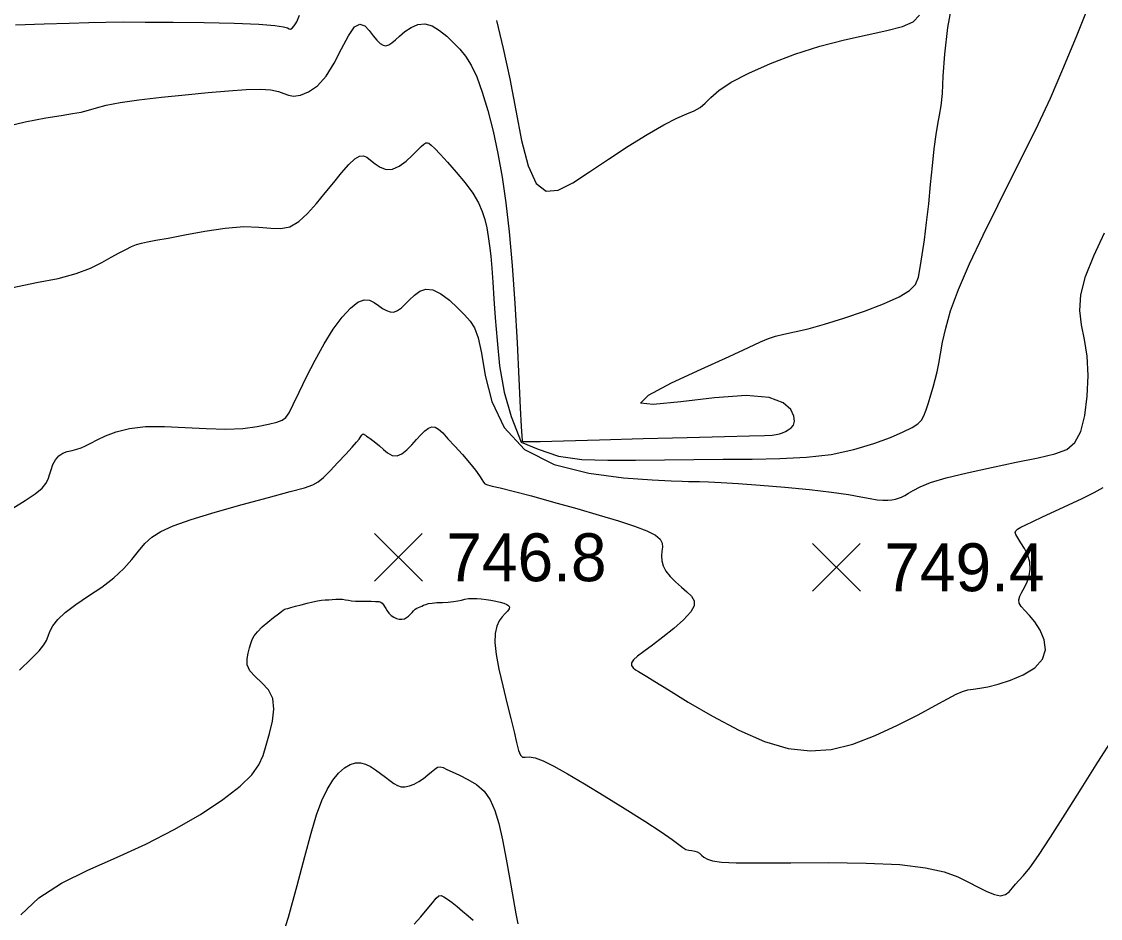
# Model space of a CAD drawing. Extents: x 2566142 to 2571431, y 418755 to 421584.
# Drawn here: x 2567172.5 to 2567510.6, y 420429 to 420710 of the extents above; entities that cross this region are included whole.
import ezdxf

# ---------------------------------------------------------------- set-up
doc = ezdxf.new("R2010")
doc.units = 0
for name, color, linetype in [('Contour_ADS_Major', 7, 'Continuous'), ('Contour_ADS_Minor', 7, 'Continuous'), ('Contour_ADS_Spot_Elevation', 7, 'Continuous')]:
    doc.layers.add(name, color=color, linetype=linetype)

# ---------------------------------------------------------------- blocks, each defined once
blk = doc.blocks.new('S750')
at = {"layer": 'Contour_ADS_Spot_Elevation'}
for p, q in [((-0.5, 0.498), (0.5, -0.498)), ((-0.498, -0.5), (0.498, 0.5))]:
    blk.add_line(p, q, dxfattribs=at)

msp = doc.modelspace()

# ---------------------------------------------------------------- linework, layer by layer
at = {"layer": 'Contour_ADS_Major'}
for points in [[(2567288.05, 420618.97), (2567289.21, 420618.95), (2567290.36, 420619.41), (2567291.53, 420620.26), (2567292.77, 420621.43), (2567294.12, 420622.79), (2567295.61, 420624.23), (2567297.28, 420625.45), (2567299.2, 420626.13), (2567301.42, 420625.94), (2567303.93, 420624.68), (2567306.57, 420622.66), (2567309.11, 420620.31), (2567311.33, 420618.06), (2567313.07, 420616.14), (2567314.43, 420614), (2567315.55, 420610.9), (2567316.59, 420606.07), (2567317.81, 420599.12), (2567319.91, 420590.95), (2567323.74, 420582.79), (2567330.09, 420575.9), (2567339.38, 420571.21), (2567350.31, 420568.44), (2567361.14, 420567.04), (2567370.15, 420566.42), (2567376.09, 420566.1), (2567379.51, 420565.94), (2567381.46, 420565.88), (2567382.95, 420565.86), (2567384.9, 420565.83), (2567387.72, 420565.74), (2567391.68, 420565.55), (2567397.06, 420565.22), (2567403.95, 420564.71), (2567411.69, 420564.07), (2567419.42, 420563.34), (2567426.27, 420562.56), (2567431.59, 420561.8), (2567435.52, 420561.11), (2567438.42, 420560.54), (2567440.62, 420560.14), (2567442.43, 420559.97), (2567443.94, 420559.98), (2567445.22, 420560.12), (2567446.32, 420560.35), (2567447.3, 420560.63), (2567448.25, 420560.99), (2567449.26, 420561.48), (2567450.42, 420562.17), (2567451.89, 420563.08), (2567454.05, 420564.2), (2567457.34, 420565.52), (2567462.19, 420567.01), (2567468.81, 420568.63), (2567476.47, 420570.29), (2567484.21, 420571.88), (2567491.06, 420573.28), (2567496.29, 420574.5), (2567500.01, 420575.94), (2567502.59, 420578.12), (2567504.38, 420581.56), (2567505.67, 420586.57), (2567506.46, 420592.64), (2567506.74, 420599.06), (2567506.44, 420605.12), (2567505.61, 420610.31), (2567504.67, 420614.93), (2567504.1, 420619.45), (2567504.39, 420624.38), (2567505.92, 420630.1), (2567508.51, 420636.59), (2567511.88, 420643.75)], [(2567169.79, 420557.49), (2567173.66, 420559.86), (2567176.82, 420561.99), (2567178.93, 420563.74), (2567180.16, 420565.21), (2567180.84, 420566.57), (2567181.28, 420567.99), (2567181.76, 420569.56), (2567182.36, 420571.19), (2567183.15, 420572.69), (2567184.16, 420573.92), (2567185.42, 420574.74), (2567186.86, 420575.25), (2567188.36, 420575.61), (2567189.82, 420575.95), (2567191.18, 420576.41), (2567192.58, 420577.03), (2567194.21, 420577.84), (2567196.24, 420578.88), (2567198.87, 420580.13), (2567202.19, 420581.4), (2567206.32, 420582.46), (2567211.36, 420583.09), (2567217.32, 420583.14), (2567223.82, 420582.82), (2567230.38, 420582.42), (2567236.54, 420582.24), (2567241.89, 420582.48), (2567246.34, 420583.06), (2567249.87, 420583.79), (2567252.47, 420584.5), (2567254.19, 420585.11), (2567255.36, 420585.94), (2567256.38, 420587.41), (2567257.66, 420589.95), (2567259.51, 420593.81), (2567261.85, 420598.63), (2567264.52, 420603.87), (2567267.35, 420609), (2567270.21, 420613.56), (2567272.97, 420617.35), (2567275.56, 420620.22), (2567277.87, 420622.05), (2567279.85, 420622.77), (2567281.55, 420622.63), (2567283.03, 420621.93), (2567284.37, 420620.99), (2567285.64, 420620.1), (2567286.86, 420619.39), (2567288.05, 420618.97)]]:
    msp.add_lwpolyline(points, dxfattribs=at)
at = {"layer": 'Contour_ADS_Minor'}
for points in [[(2567283.85, 420704.13), (2567284.87, 420703.14), (2567285.81, 420702.56), (2567286.71, 420702.4), (2567287.59, 420702.64), (2567288.54, 420703.26), (2567289.65, 420704.2), (2567290.99, 420705.41), (2567292.65, 420706.8), (2567294.57, 420708.11), (2567296.68, 420709.03), (2567298.92, 420709.26), (2567301.22, 420708.59), (2567303.52, 420707.2), (2567305.76, 420705.36), (2567307.87, 420703.34), (2567309.82, 420701.32), (2567311.64, 420699.08), (2567313.39, 420696.28), (2567315.13, 420692.62), (2567316.88, 420687.86), (2567318.62, 420682.13), (2567320.27, 420675.65), (2567321.8, 420668.64), (2567323.14, 420661.22), (2567324.31, 420653.14), (2567325.35, 420644.04), (2567326.26, 420633.57), (2567327.07, 420621.66), (2567327.78, 420609.35), (2567328.36, 420598), (2567328.79, 420588.93), (2567329.07, 420583.11), (2567329.23, 420580.02), (2567329.34, 420578.77), (2567329.43, 420578.47), (2567329.74, 420578.38), (2567331.23, 420578.36), (2567335.04, 420578.44), (2567342.3, 420578.63), (2567353.59, 420578.94), (2567367.25, 420579.32), (2567381.03, 420579.7), (2567392.73, 420580.01), (2567400.64, 420580.21), (2567405.28, 420580.32), (2567407.71, 420580.41), (2567408.99, 420580.55), (2567410, 420580.77), (2567410.95, 420581.08), (2567411.86, 420581.5), (2567412.76, 420582.02), (2567413.64, 420582.66), (2567414.36, 420583.52), (2567414.72, 420584.72), (2567414.54, 420586.35), (2567413.54, 420588.44), (2567411.16, 420590.56), (2567406.73, 420592.18), (2567399.6, 420592.79), (2567389.67, 420592.11), (2567379.06, 420590.84), (2567370.45, 420589.96), (2567366.5, 420590.43), (2567369.01, 420592.89), (2567376.22, 420596.75), (2567385.5, 420601.1), (2567394.2, 420605.02), (2567400.28, 420607.8), (2567404.09, 420609.58), (2567406.61, 420610.65), (2567408.77, 420611.36), (2567411.4, 420612), (2567414.75, 420612.73), (2567418.95, 420613.72), (2567424.1, 420615.12), (2567430.18, 420617), (2567436.59, 420619.22), (2567442.61, 420621.53), (2567447.5, 420623.73), (2567450.72, 420625.68), (2567452.57, 420627.62), (2567453.53, 420629.91), (2567454.12, 420632.89), (2567454.72, 420636.83), (2567455.39, 420641.59), (2567456.09, 420647), (2567456.76, 420652.84), (2567457.37, 420658.88), (2567457.94, 420664.77), (2567458.49, 420670.12), (2567459.05, 420674.54), (2567459.61, 420677.85), (2567460.16, 420680.6), (2567460.65, 420683.53), (2567461.04, 420687.41), (2567461.34, 420692.81), (2567461.82, 420699.77), (2567462.78, 420708.15), (2567464.56, 420717.81)], [(2567453.35, 420583.95), (2567454.45, 420585.08), (2567455.24, 420586.49), (2567455.99, 420588.34), (2567456.74, 420590.56), (2567457.47, 420592.98), (2567458.15, 420595.43), (2567458.78, 420597.8), (2567459.37, 420600.22), (2567459.93, 420602.86), (2567460.49, 420605.88), (2567461.13, 420609.49), (2567462.08, 420613.89), (2567463.62, 420619.32), (2567466.05, 420626.03), (2567469.55, 420634.1), (2567473.8, 420643.07), (2567478.41, 420652.37), (2567482.95, 420661.38), (2567487.13, 420669.71), (2567491.04, 420677.73), (2567494.87, 420686), (2567498.83, 420695.08), (2567503.05, 420705.32), (2567507.46, 420716.2)], [(2567187.41, 420709.51), (2567193.57, 420709.68), (2567198.88, 420709.78), (2567204.42, 420709.83), (2567211.23, 420709.82), (2567219.99, 420709.76), (2567229.74, 420709.63), (2567239.15, 420709.43), (2567246.85, 420709.14), (2567251.86, 420708.75), (2567254.59, 420708.34), (2567255.84, 420707.96), (2567256.36, 420707.7), (2567256.82, 420707.63), (2567257.35, 420707.88), (2567257.99, 420708.6), (2567258.75, 420709.9), (2567259.65, 420711.92)], [(2567321.35, 420710.25), (2567323.45, 420701.54), (2567325.5, 420692), (2567327.36, 420682.09), (2567329.21, 420672.67), (2567331.26, 420664.72), (2567333.75, 420659.22), (2567336.89, 420656.86), (2567340.71, 420657.17), (2567345.24, 420659.43), (2567350.5, 420662.88), (2567356.43, 420666.86), (2567362.61, 420670.9), (2567368.55, 420674.63), (2567373.76, 420677.65), (2567377.86, 420679.7), (2567380.98, 420681.03), (2567383.32, 420682.02), (2567385.14, 420683.05), (2567386.7, 420684.43), (2567388.48, 420686.21), (2567391.03, 420688.39), (2567394.87, 420690.95), (2567400.36, 420693.84), (2567407.16, 420696.85), (2567414.77, 420699.74), (2567422.66, 420702.28), (2567430.36, 420704.27), (2567437.48, 420705.85), (2567443.66, 420707.18), (2567448.53, 420708.46), (2567451.87, 420709.91), (2567453.92, 420711.92)], [(2567165.3, 420676.58), (2567173.62, 420678.5), (2567180.11, 420679.77), (2567184.93, 420680.58), (2567188.5, 420681.12), (2567191.22, 420681.61), (2567193.54, 420682.22), (2567195.97, 420682.94), (2567199.08, 420683.74), (2567203.41, 420684.59), (2567209.32, 420685.44), (2567216.34, 420686.27), (2567223.79, 420687.04), (2567231, 420687.73), (2567237.41, 420688.29), (2567242.85, 420688.66), (2567247.29, 420688.79), (2567250.66, 420688.6), (2567253.01, 420688.09), (2567254.68, 420687.44), (2567256.12, 420686.87), (2567257.74, 420686.63), (2567259.89, 420686.92), (2567262.45, 420687.94), (2567265.21, 420689.86), (2567267.94, 420692.85), (2567270.49, 420696.93), (2567272.81, 420701.43), (2567274.92, 420705.49), (2567276.83, 420708.28), (2567278.55, 420709.2), (2567280.1, 420708.62), (2567281.49, 420707.19), (2567282.73, 420705.52), (2567283.85, 420704.13)], [(2567170.65, 420708.95), (2567179.64, 420709.27), (2567187.41, 420709.51)], [(2567169.81, 420626.6), (2567177.23, 420628.2), (2567184.02, 420629.48), (2567189.62, 420630.99), (2567194.11, 420632.71), (2567197.71, 420634.47), (2567200.64, 420636.11), (2567203.08, 420637.49), (2567205.16, 420638.6), (2567206.95, 420639.46), (2567208.55, 420640.1), (2567210.08, 420640.56), (2567211.94, 420640.96), (2567214.57, 420641.44), (2567218.41, 420642.15), (2567223.7, 420643.17), (2567229.9, 420644.28), (2567236.29, 420645.22), (2567242.13, 420645.71), (2567246.85, 420645.59), (2567250.63, 420645.23), (2567253.76, 420645.1), (2567256.59, 420645.68), (2567259.38, 420647.32), (2567262.16, 420649.84), (2567264.93, 420652.93), (2567267.66, 420656.28), (2567270.32, 420659.59), (2567272.82, 420662.62), (2567275.07, 420665.15), (2567276.96, 420666.94), (2567278.43, 420667.83), (2567279.63, 420667.94), (2567280.72, 420667.44), (2567281.89, 420666.53), (2567283.28, 420665.39), (2567284.91, 420664.32), (2567286.74, 420663.64), (2567288.74, 420663.68), (2567290.88, 420664.61), (2567293, 420666.18), (2567294.96, 420667.99), (2567296.59, 420669.64), (2567297.78, 420670.83), (2567298.61, 420671.56), (2567299.2, 420671.92), (2567299.68, 420671.99), (2567300.18, 420671.82), (2567300.88, 420671.28), (2567301.97, 420670.21), (2567303.64, 420668.44), (2567305.98, 420665.89), (2567308.72, 420662.79), (2567311.48, 420659.44), (2567313.89, 420656.17), (2567315.66, 420653.2), (2567316.87, 420650.49), (2567317.68, 420647.91), (2567318.27, 420645.35), (2567318.75, 420642.67), (2567319.17, 420639.75), (2567319.55, 420636.47), (2567319.88, 420632.69), (2567320.18, 420628.29), (2567320.51, 420623.13), (2567320.93, 420617.11), (2567321.5, 420610.08), (2567322.32, 420602.09), (2567323.69, 420593.84), (2567325.95, 420586.2), (2567329.09, 420578.14), (2567334.43, 420576), (2567340.73, 420573.76), (2567348.08, 420572.78), (2567356.22, 420572.53), (2567364.91, 420572.52), (2567373.94, 420572.62), (2567383.15, 420572.76), (2567392.36, 420572.86), (2567401.4, 420572.9), (2567410.14, 420573.03), (2567418.45, 420573.45), (2567426.22, 420574.35), (2567433.29, 420575.85), (2567439.53, 420577.73), (2567444.75, 420579.7), (2567448.8, 420581.47), (2567451.57, 420582.83), (2567453.35, 420583.95)], [(2567261.17, 420563.89), (2567263.82, 420564.77), (2567265.51, 420565.73), (2567267.08, 420567.13), (2567269.18, 420569.25), (2567271.64, 420571.81), (2567274.08, 420574.4), (2567276.12, 420576.61), (2567277.48, 420578.16), (2567278.26, 420579.11), (2567278.65, 420579.65), (2567278.84, 420579.98), (2567279, 420580.24), (2567279.16, 420580.45), (2567279.31, 420580.62), (2567279.44, 420580.72), (2567279.55, 420580.76), (2567279.66, 420580.74), (2567279.77, 420580.69), (2567279.89, 420580.6), (2567280.05, 420580.49), (2567280.28, 420580.33), (2567280.61, 420580.1), (2567281.09, 420579.78), (2567281.73, 420579.33), (2567282.55, 420578.73), (2567283.52, 420577.97), (2567284.63, 420577.01), (2567285.88, 420575.87), (2567287.23, 420574.8), (2567288.67, 420574.05), (2567290.18, 420573.91), (2567291.72, 420574.55), (2567293.27, 420575.8), (2567294.79, 420577.39), (2567296.24, 420579.04), (2567297.6, 420580.52), (2567298.87, 420581.72), (2567300.03, 420582.56), (2567301.1, 420582.96), (2567302.1, 420582.87), (2567303.17, 420582.25), (2567304.47, 420581.06), (2567306.14, 420579.28), (2567308.28, 420576.95), (2567310.64, 420574.32), (2567312.91, 420571.7), (2567314.77, 420569.41), (2567315.99, 420567.68), (2567316.72, 420566.47), (2567317.22, 420565.66), (2567317.72, 420565.14), (2567318.51, 420564.79), (2567319.96, 420564.41), (2567322.49, 420563.83), (2567326.52, 420562.85), (2567332.26, 420561.33), (2567339.17, 420559.44), (2567346.5, 420557.37), (2567353.52, 420555.33), (2567359.6, 420553.5), (2567364.58, 420551.87), (2567368.43, 420550.41), (2567371.11, 420549.06), (2567372.64, 420547.8), (2567373.29, 420546.57), (2567373.36, 420545.33), (2567373.19, 420544.01), (2567373.06, 420542.59), (2567373.13, 420541.06), (2567373.52, 420539.45), (2567374.37, 420537.79), (2567375.72, 420536.08), (2567377.43, 420534.39), (2567379.27, 420532.76), (2567381, 420531.26), (2567382.41, 420529.89), (2567383.25, 420528.52), (2567383.26, 420526.95), (2567382.2, 420525), (2567379.94, 420522.55), (2567376.85, 420519.81), (2567373.44, 420517.08), (2567370.19, 420514.62), (2567367.53, 420512.65), (2567365.54, 420511.14), (2567364.22, 420509.97), (2567363.59, 420509.03), (2567363.6, 420508.23), (2567364.11, 420507.52), (2567364.93, 420506.89), (2567365.88, 420506.31), (2567366.89, 420505.7), (2567368.4, 420504.77), (2567370.98, 420503.18), (2567375.19, 420500.57), (2567381.38, 420496.77), (2567388.98, 420492.32), (2567397.23, 420487.96), (2567405.35, 420484.39), (2567412.76, 420482.21)], [(2567171.83, 420506.75), (2567175.57, 420510.28), (2567178.06, 420512.85), (2567179.51, 420514.66), (2567180.31, 420516.06), (2567180.82, 420517.37), (2567181.41, 420518.88), (2567182.33, 420520.63), (2567183.86, 420522.62), (2567186.23, 420524.87), (2567189.58, 420527.34), (2567193.55, 420530.01), (2567197.66, 420532.81), (2567201.44, 420535.69), (2567204.53, 420538.59), (2567207.03, 420541.41), (2567209.17, 420544.05), (2567211.19, 420546.39), (2567213.35, 420548.39), (2567216.14, 420550.19), (2567220.07, 420551.99), (2567225.67, 420553.97), (2567233.18, 420556.26), (2567241.66, 420558.65), (2567249.91, 420560.88), (2567256.71, 420562.68), (2567261.17, 420563.89)], [(2567412.76, 420482.21), (2567419.6, 420481.43), (2567426.23, 420481.94), (2567432.97, 420483.61), (2567440.03, 420486.26), (2567447.03, 420489.48), (2567453.45, 420492.77), (2567458.78, 420495.67), (2567462.65, 420497.79), (2567465.35, 420499.19), (2567467.31, 420500.05), (2567468.97, 420500.55), (2567470.71, 420500.84), (2567472.76, 420501.11), (2567475.29, 420501.55), (2567478.47, 420502.32), (2567482.34, 420503.57), (2567486.39, 420505.31), (2567489.97, 420507.52), (2567492.44, 420510.15), (2567493.33, 420513.15), (2567492.92, 420516.29), (2567491.65, 420519.29), (2567489.99, 420521.91), (2567488.33, 420523.93), (2567486.87, 420525.46), (2567485.73, 420526.67), (2567485.06, 420527.73), (2567484.95, 420528.78), (2567485.29, 420529.92), (2567485.93, 420531.2), (2567486.74, 420532.68), (2567487.56, 420534.4), (2567488.23, 420536.34), (2567488.59, 420538.41), (2567488.49, 420540.58), (2567487.83, 420542.77), (2567486.8, 420544.85), (2567485.67, 420546.7), (2567484.68, 420548.19), (2567484.07, 420549.23), (2567483.85, 420549.92), (2567484.04, 420550.43), (2567484.63, 420550.92), (2567485.64, 420551.51), (2567487.18, 420552.31), (2567489.39, 420553.38), (2567492.4, 420554.78), (2567496.25, 420556.56), (2567500.55, 420558.54), (2567504.82, 420560.56), (2567508.56, 420562.4), (2567511.44, 420563.94)], [(2567172.31, 420430.15), (2567177.89, 420435.45), (2567185.02, 420440.04), (2567193.32, 420444.14), (2567202.3, 420448.1), (2567211.48, 420452.24), (2567220.37, 420456.79), (2567228.54, 420461.55), (2567235.57, 420466.19), (2567241.02, 420470.39), (2567244.66, 420473.94), (2567246.86, 420477.05), (2567248.18, 420480.05), (2567249.16, 420483.26), (2567250.23, 420486.9), (2567251.16, 420490.76), (2567251.62, 420494.52), (2567251.25, 420497.88), (2567249.85, 420500.6), (2567247.82, 420502.81), (2567245.7, 420504.72), (2567244.04, 420506.53), (2567243.25, 420508.42), (2567243.17, 420510.31), (2567243.52, 420512.13), (2567243.99, 420513.75), (2567244.39, 420515.12), (2567244.8, 420516.33), (2567245.42, 420517.51), (2567246.43, 420518.8), (2567247.93, 420520.28), (2567249.71, 420521.83), (2567251.49, 420523.26), (2567252.98, 420524.41), (2567253.96, 420525.15), (2567254.5, 420525.55), (2567254.77, 420525.72), (2567254.91, 420525.77), (2567255.06, 420525.83), (2567255.37, 420525.92), (2567255.94, 420526.09), (2567256.92, 420526.37), (2567258.36, 420526.77), (2567260.12, 420527.26), (2567261.98, 420527.74), (2567263.74, 420528.16), (2567265.24, 420528.45)], [(2567265.24, 420528.45), (2567266.51, 420528.64), (2567267.65, 420528.76), (2567268.75, 420528.84), (2567269.88, 420528.92), (2567271.02, 420528.98), (2567272.11, 420528.99), (2567273.12, 420528.95), (2567274.03, 420528.82), (2567274.93, 420528.66), (2567275.93, 420528.49), (2567277.17, 420528.37), (2567278.7, 420528.33), (2567280.38, 420528.34), (2567282.02, 420528.35), (2567283.42, 420528.32), (2567284.43, 420528.22), (2567285.11, 420528.02), (2567285.56, 420527.71), (2567285.91, 420527.27), (2567286.24, 420526.7), (2567286.62, 420526.03), (2567287.07, 420525.31), (2567287.64, 420524.59), (2567288.35, 420523.92), (2567289.16, 420523.35), (2567290.02, 420522.92), (2567290.89, 420522.69), (2567291.71, 420522.69), (2567292.47, 420522.88), (2567293.16, 420523.24), (2567293.8, 420523.71), (2567294.36, 420524.26), (2567294.88, 420524.84), (2567295.37, 420525.38), (2567295.87, 420525.84), (2567296.38, 420526.17), (2567296.9, 420526.42), (2567297.44, 420526.63), (2567297.97, 420526.84), (2567298.51, 420527.08), (2567299.15, 420527.35), (2567299.99, 420527.6), (2567301.14, 420527.79), (2567302.66, 420527.91), (2567304.4, 420527.99), (2567306.19, 420528.08), (2567307.84, 420528.22), (2567309.21, 420528.45), (2567310.37, 420528.72), (2567311.44, 420528.98), (2567312.55, 420529.18), (2567313.78, 420529.26), (2567315.14, 420529.23), (2567316.58, 420529.11), (2567318.09, 420528.92), (2567319.61, 420528.68), (2567321.09, 420528.39), (2567322.46, 420528.07), (2567323.64, 420527.72), (2567324.57, 420527.34), (2567325.19, 420526.92), (2567325.46, 420526.46), (2567325.34, 420525.92), (2567324.81, 420525.29), (2567324, 420524.51), (2567323.06, 420523.5), (2567322.15, 420522.19), (2567321.4, 420520.5), (2567320.94, 420518.29), (2567320.84, 420515.4), (2567321.2, 420511.66), (2567322.07, 420507.03), (2567323.28, 420501.84), (2567324.61, 420496.55), (2567325.85, 420491.62), (2567326.84, 420487.41), (2567327.6, 420484.06), (2567328.23, 420481.61), (2567328.82, 420480.11), (2567329.47, 420479.53), (2567330.34, 420479.5), (2567331.6, 420479.58), (2567333.42, 420479.33), (2567335.97, 420478.38), (2567339.35, 420476.68), (2567343.63, 420474.25), (2567348.89, 420471.11), (2567355.09, 420467.34), (2567361.64, 420463.3), (2567367.82, 420459.42), (2567372.9, 420456.11), (2567376.36, 420453.7), (2567378.49, 420452.11), (2567379.76, 420451.15), (2567380.66, 420450.62), (2567381.58, 420450.36), (2567382.53, 420450.22), (2567383.45, 420450.09), (2567384.25, 420449.84), (2567384.91, 420449.38)], [(2567384.91, 420449.38), (2567385.55, 420448.77), (2567386.32, 420448.12), (2567387.4, 420447.5), (2567389.03, 420447.01), (2567391.81, 420446.65), (2567396.43, 420446.44), (2567403.57, 420446.37), (2567413.58, 420446.43), (2567425.28, 420446.46), (2567437.16, 420446.32), (2567447.71, 420445.82), (2567455.76, 420444.86), (2567461.6, 420443.52), (2567465.89, 420441.96), (2567469.27, 420440.31), (2567472.28, 420438.73), (2567474.98, 420437.38), (2567477.33, 420436.45), (2567479.27, 420436.1), (2567480.79, 420436.46), (2567481.98, 420437.34), (2567483, 420438.51), (2567483.96, 420439.72), (2567485.04, 420440.88), (2567486.44, 420442.39), (2567488.42, 420444.81), (2567491.21, 420448.7), (2567494.96, 420454.42), (2567499.49, 420461.59), (2567504.5, 420469.6), (2567509.71, 420477.88), (2567514.85, 420485.87)], [(2567253.06, 420419.56), (2567256.17, 420429.32), (2567258.9, 420439.27), (2567261.24, 420448.34), (2567263.23, 420455.69), (2567264.98, 420461.43), (2567266.62, 420465.89), (2567268.27, 420469.41), (2567270.04, 420472.26), (2567271.88, 420474.52), (2567273.72, 420476.18), (2567275.51, 420477.25), (2567277.18, 420477.74), (2567278.76, 420477.73), (2567280.31, 420477.3), (2567281.86, 420476.54), (2567283.44, 420475.53), (2567285.02, 420474.4), (2567286.53, 420473.23), (2567287.92, 420472.16), (2567289.14, 420471.27), (2567290.28, 420470.62), (2567291.42, 420470.25), (2567292.65, 420470.2), (2567294.04, 420470.49), (2567295.53, 420471.07), (2567297.04, 420471.88), (2567298.48, 420472.85), (2567299.79, 420473.91), (2567300.96, 420474.93), (2567301.98, 420475.78), (2567302.88, 420476.32), (2567303.69, 420476.45), (2567304.59, 420476.21), (2567305.77, 420475.65), (2567307.44, 420474.85), (2567309.72, 420473.83), (2567312.36, 420472.55), (2567315.06, 420470.9), (2567317.47, 420468.8)], [(2567317.47, 420468.8), (2567319.37, 420466.15), (2567320.83, 420462.81), (2567322.04, 420458.67), (2567323.17, 420453.58), (2567324.33, 420447.55), (2567325.49, 420441.18), (2567326.54, 420435.21), (2567327.39, 420430.4), (2567328.06, 420427.29)], [(2567295.52, 420427.15), (2567297.65, 420429.44), (2567299.66, 420431.85), (2567301.31, 420433.91), (2567302.47, 420435.3), (2567303.29, 420436), (2567304.01, 420436.12), (2567304.85, 420435.76), (2567306, 420435.01), (2567307.43, 420433.96), (2567309.03, 420432.69), (2567310.73, 420431.28), (2567312.44, 420429.82), (2567314.06, 420428.4)]]:
    msp.add_lwpolyline(points, dxfattribs=at)

# ---------------------------------------------------------------- block references
at = {"layer": 'Contour_ADS_Spot_Elevation', "xscale": 15, "yscale": 15}
for p in [(2567290.62, 420542.12), (2567427.85, 420538.99)]:
    msp.add_blockref('S750', p, dxfattribs=at)

# ---------------------------------------------------------------- texts
at = {"layer": 'Contour_ADS_Spot_Elevation'}
for s, p in [('746.8', (2567305.62, 420534.62)), ('749.4', (2567442.85, 420531.49))]:
    msp.add_text(s, height=15, dxfattribs=at).set_placement(p)

doc.saveas('drawing.dxf')
